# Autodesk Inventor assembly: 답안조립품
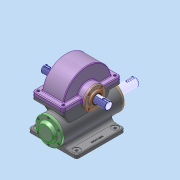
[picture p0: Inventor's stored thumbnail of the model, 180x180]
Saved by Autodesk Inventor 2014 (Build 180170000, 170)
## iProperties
Created: 2023-07
Part Number: 답안조립품
Document SubType Name: Assembly
Designer: dg
Author: dg
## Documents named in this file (14)
- C:\Users\dg\Desktop\730706V1003\답안조립품.iam
- C:\Users\dg\Desktop\730706V1003\본체.ipt
- C:\Users\dg\Desktop\730706V1003\웜 샤프트.ipt
- C:\Users\dg\Desktop\730706V1003\깊은 홈 볼 베어링 6209.ipt
- C:\Users\dg\Desktop\730706V1003\뒤커버.ipt
- C:\Users\dg\Desktop\730706V1003\앞커버.ipt
- C:\Users\dg\Desktop\730706V1003\본체 커버.ipt
- C:\Users\dg\Desktop\730706V1003\웜 휠.ipt
- C:\Users\dg\Desktop\730706V1003\깊은 홈 볼 베어링 6206.ipt
- C:\Users\dg\Desktop\730706V1003\서브커버.ipt
- C:\Users\dg\Desktop\730706V1003\오일 실 30 42 7.ipt
- C:\Users\dg\Desktop\730706V1003\오일 실 35 55 11.ipt
- C:\Users\dg\Desktop\730706V1003\육각 소켓 머리 볼트 M6 x 20.ipt
- C:\Users\dg\Desktop\730706V1003\육각 소켓 머리 볼트 M5 x 12.ipt
